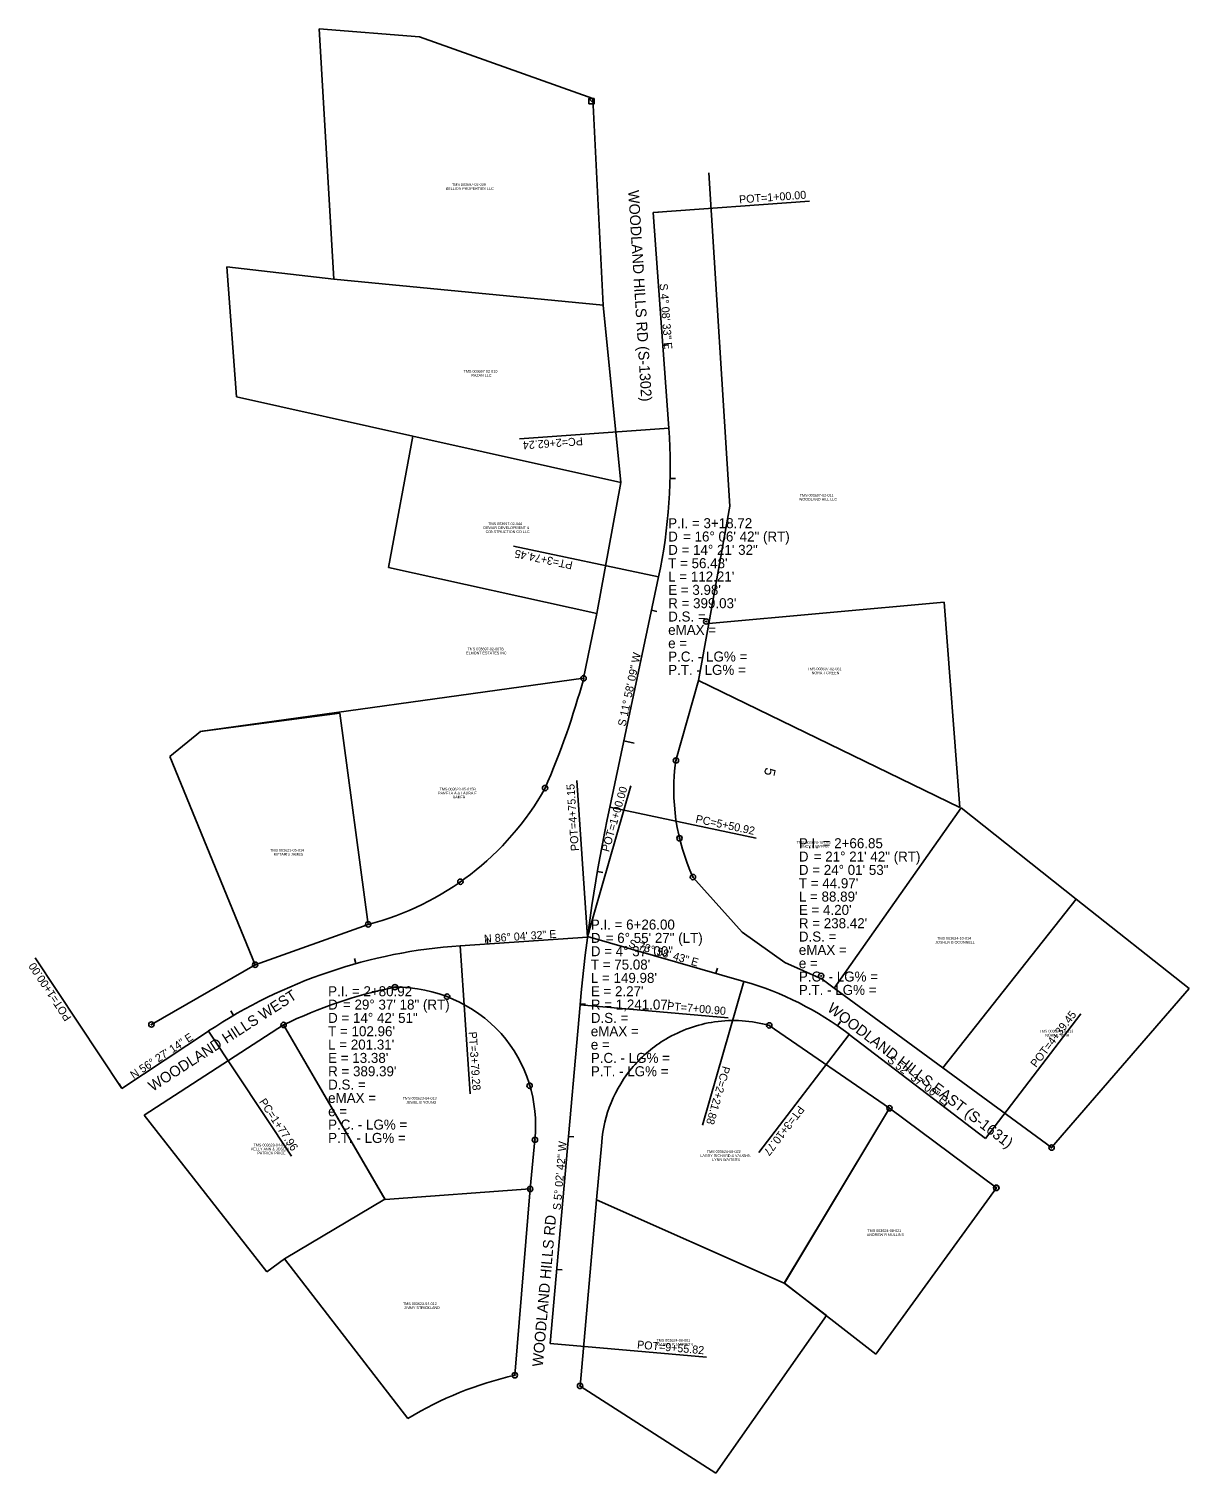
# Model space of a CAD drawing. Extents: x 1963319 to 1964189, y 803266 to 804349.
import ezdxf

# ---------------------------------------------------------------- set-up
doc = ezdxf.new("R2010")
doc.units = 0
for name, color, linetype in [('RD_EX_DV_Prop', 7, 'Continuous'), ('RD_EX_DV_PropPin', 7, 'Continuous'), ('RD_EX_DV_TX_Prop', 7, 'Continuous'), ('RD_HC_CL', 7, 'Continuous'), ('RD_HC_Data', 7, 'Continuous'), ('RD_HC_Data_Tic', 7, 'Continuous'), ('RD_TX_RoadID', 7, 'Continuous')]:
    doc.layers.add(name, color=color, linetype=linetype)

msp = doc.modelspace()

# ---------------------------------------------------------------- linework, layer by layer
at = {"layer": 'RD_EX_DV_Prop'}
for p, q in [((1963547.2, 804161.8), (1963536.2, 804349.4)), ((1963536.2, 804349.4), (1963611.4, 804343.4)), ((1963611.4, 804343.4), (1963741.5, 804297.2)), ((1963741.5, 804297.2), (1963749.2, 804142.2)), ((1963844.2, 803991.6), (1963828.6, 804241.4)), ((1963474.2, 804073.5), (1963467, 804171)), ((1963547.2, 804161.8), (1963467, 804171)), ((1963749.2, 804142.2), (1963547.2, 804161.8)), ((1963762.6, 804009.3), (1963749.2, 804142.2)), ((1963606.4, 804044), (1963474.2, 804073.5)), ((1963588.2, 803945.6), (1963606.4, 804044)), ((1963606.4, 804044), (1963762.6, 804009.3)), ((1963762.6, 804009.3), (1963744.4, 803911)), ((1963828.4, 803903.4), (1963844.2, 803991.6)), ((1963744.4, 803911), (1963588.2, 803945.6)), ((1963828.4, 803903.4), (1964004.9, 803919.4)), ((1964004.9, 803919.4), (1963828.4, 803903.4)), ((1964004.9, 803919.4), (1964016.8, 803765.6)), ((1963734.6, 803862.4), (1963744.4, 803911)), ((1963820.8, 803860.8), (1963828.4, 803903.4)), ((1963446.9, 803822.5), (1963734.6, 803862.4)), ((1963803.8, 803800.8), (1963820.8, 803860.8)), ((1964016.8, 803765.6), (1963820.8, 803860.8)), ((1963424.3, 803803.9), (1963447.3, 803822.6)), ((1964017.6, 803765.2), (1963922.5, 803630.1)), ((1964017.6, 803765.2), (1964103.9, 803696.9)), ((1963816.6, 803713.4), (1963853.5, 803672.1)), ((1964103.9, 803696.9), (1964004, 803570.3)), ((1964103.9, 803696.9), (1964188.7, 803629.9)), ((1963853.5, 803672.1), (1963885.6, 803649.2)), ((1963488.4, 803647.6), (1963410.5, 803602.8)), ((1963885.6, 803649.2), (1963913.4, 803636.9)), ((1963913.4, 803636.9), (1963922.5, 803630.1)), ((1963922.5, 803630.1), (1964004, 803570.3)), ((1964188.7, 803629.9), (1964085.5, 803510.5)), ((1963405, 803534.8), (1963509.6, 803602.5)), ((1963585.7, 803471.5), (1963509.6, 803602.5)), ((1963509.6, 803602.5), (1963585.6, 803471.8)), ((1964004, 803570.3), (1964085.5, 803510.5)), ((1963497.1, 803417.4), (1963405, 803534.8)), ((1963963.9, 803540.1), (1963885, 803408.8)), ((1963698.1, 803516.3), (1963694.5, 803479.5)), ((1963694.5, 803479.5), (1963585.7, 803471.5)), ((1963694.5, 803479.5), (1963683, 803339.8)), ((1964044.1, 803480.4), (1963953.6, 803355.7)), ((1963585.6, 803471.8), (1963510.3, 803427)), ((1963510.3, 803427), (1963497.1, 803417.4)), ((1963602.8, 803307.4), (1963510.3, 803427)), ((1963916.8, 803384.7), (1963833.8, 803266.4))]:
    msp.add_line(p, q, dxfattribs=at)
for points in [[(1963447.3, 803822.6), (1963551.7, 803836.3)], [(1963551.7, 803836.3), (1963573, 803677.9)], [(1963488.4, 803647.6), (1963424.3, 803803.9)], [(1963573, 803677.9), (1963488.4, 803647.6)], [(1963873.8, 803602.1), (1963963.9, 803540.1)], [(1963885.2, 803408.9), (1963964, 803540)], [(1963964, 803540), (1964044.1, 803480.4)], [(1963744.3, 803471.3), (1963748.2, 803514.6)], [(1963732, 803331.6), (1963744.3, 803471.3)], [(1963885, 803408.8), (1963744.3, 803471.3)], [(1963744.3, 803471.3), (1963885, 803408.8)], [(1963885, 803408.8), (1963916.8, 803384.7)], [(1963953.6, 803355.7), (1963885.2, 803408.9)], [(1963833.8, 803266.4), (1963732, 803331.6)]]:
    msp.add_lwpolyline(points, dxfattribs=at)
for centre, radius, start, end in [((1963137.1, 804026.5), 619.7, 336.57, 344.643), ((1963958.5, 803778.9), 156.3, 171.9625, 204.7949), ((1963519.4, 803884.7), 213.7, 284.5471, 330.6702), ((1963659, 803299.8), 337.5, 101.2656, 116.2656), ((1963594, 803524.4), 106.4, 42.2772, 90.5106), ((1963594, 803527.1), 104.6, 354.0595, 41.1595), ((1963742.6, 803076.7), 269.7, 102.7772, 121.221)]:
    msp.add_arc(centre, radius, start, end, dxfattribs=at)
for major_axis, start_param, end_param in [((-64.8, -74.9), 3.997191, 4.391483), ((64.8, 74.9), 0.437838, 0.855627), ((-64.8, -74.9), 4.391466, 4.714868), ((-64.8, -74.9), 4.714866, 5.038268), ((-64.8, -74.9), 5.038267, 5.346337)]:
    msp.add_ellipse((1963846.8, 803506.8), major_axis=major_axis, ratio=0.998737, start_param=start_param, end_param=end_param, dxfattribs=at)
at = {"layer": 'RD_EX_DV_PropPin'}
msp.add_line((1963742.4, 804293.2), (1963738.4, 804297.2), dxfattribs=at)
msp.add_lwpolyline([(1963738.4, 804293.2), (1963738.4, 804297.2), (1963742.4, 804297.2), (1963742.4, 804293.2)], close=True, dxfattribs=at)
for centre, radius in [((1963826.5, 803905), 2), ((1963826.5, 803905), 0.25), ((1963826.5, 803905), 0.0001), ((1963734.6, 803862.4), 2), ((1963734.6, 803862.4), 0.25), ((1963734.6, 803862.4), 0.0001), ((1963803.8, 803800.8), 2), ((1963803.8, 803800.8), 0.25), ((1963803.7, 803800.8), 0.0001), ((1963705.7, 803780.1), 2), ((1963705.7, 803780.1), 0.25), ((1963705.6, 803780.1), 0.0001), ((1963806.5, 803742.5), 2), ((1963806.5, 803742.5), 0.25), ((1963806.5, 803742.6), 0.0001), ((1963642.2, 803709.9), 2), ((1963642.2, 803709.9), 0.25), ((1963642.2, 803709.9), 0.0001), ((1963816.6, 803713.4), 2), ((1963816.6, 803713.4), 0.25), ((1963816.6, 803713.4), 0.0001), ((1963573, 803677.9), 2), ((1963573, 803677.9), 0.25), ((1963573, 803677.9), 0.0001), ((1963488.3, 803647.6), 2), ((1963488.3, 803647.6), 0.25), ((1963488.3, 803647.6), 0.0001), ((1963912.7, 803639.2), 2), ((1963593.1, 803630.8), 2), ((1963593.1, 803630.8), 0.25), ((1963593, 803630.9), 0.0001), ((1963912.7, 803639.2), 0.25), ((1963912.7, 803639.2), 0.0001), ((1963632.2, 803623.7), 2), ((1963632.2, 803623.7), 0.25), ((1963632.1, 803623.7), 0.0001), ((1963410.5, 803602.8), 2), ((1963410.5, 803602.8), 0.25), ((1963410.5, 803602.9), 0.0001), ((1963509.6, 803602.5), 2), ((1963509.6, 803602.5), 0.25), ((1963509.6, 803602.5), 0.0001), ((1963873.8, 803602.1), 2), ((1963873.8, 803602.1), 0.25), ((1963873.8, 803602.1), 0.0001), ((1963694.1, 803556.9), 2), ((1963694.1, 803556.9), 0.25), ((1963694, 803556.9), 0.0001), ((1963964, 803540), 2), ((1963964, 803540), 0.25), ((1963964, 803540.1), 0.0001), ((1963698.1, 803516.3), 2), ((1963698.1, 803516.3), 0.25), ((1963698, 803516.3), 0.0001), ((1964085.5, 803510.5), 2), ((1964085.5, 803510.5), 0.25), ((1964085.4, 803510.5), 0.0001), ((1963694.5, 803479.5), 2), ((1963694.5, 803479.5), 0.25), ((1963694.5, 803479.5), 0.0001), ((1964044, 803480.2), 2), ((1964044.1, 803480.4), 2), ((1964044, 803480.2), 0.25), ((1964044.1, 803480.4), 0.25), ((1964043.9, 803480.2), 0.0001), ((1964044, 803480.4), 0.0001), ((1963683, 803339.8), 2), ((1963683, 803339.8), 0.25), ((1963683, 803339.8), 0.0001), ((1963731.9, 803331.8), 2), ((1963731.9, 803331.8), 0.25), ((1963731.9, 803331.9), 0.0001)]:
    msp.add_circle(centre, radius, dxfattribs=at)
at = {"layer": 'RD_HC_CL'}
for p, q in [((1963786.7, 804211.8), (1963798.4, 804050)), ((1963790.8, 803938.4), (1963754.2, 803765.8)), ((1963641.9, 803661.9), (1963737.6, 803668.4)), ((1963737.6, 803668.8), (1963854.8, 803635.1)), ((1963732, 803617.5), (1963709.6, 803363.6)), ((1963388.4, 803554.8), (1963453.4, 803597.9)), ((1963933.7, 803595.4), (1964036, 803517.3))]:
    msp.add_line(p, q, dxfattribs=at)
for centre, radius, start, end in [((1963400.5, 804021.2), 399, 348.0309, 4.1425), ((1964968.3, 803508.4), 1241.1, 168.0309, 174.9549), ((1963668.6, 803273.4), 389.4, 93.9245, 123.546), ((1963789, 803406), 238.4, 52.6167, 73.9785)]:
    msp.add_arc(centre, radius, start, end, dxfattribs=at)
at = {"layer": 'RD_HC_Data'}
for p, q in [((1963786.7, 804211.8), (1963904.1, 804220.3)), ((1963798.4, 804050), (1963686.5, 804041.9)), ((1963790.8, 803938.4), (1963682, 803961.5)), ((1963737.6, 803668.4), (1963729.5, 803785.8)), ((1963737.6, 803668.8), (1963770.1, 803781.9)), ((1963754.2, 803765.8), (1963863.9, 803742.5)), ((1963388.4, 803554.8), (1963323.4, 803652.9)), ((1963641.9, 803661.9), (1963649.6, 803550.8)), ((1963854.8, 803635.1), (1963823.8, 803527.2)), ((1963732, 803617.5), (1963842.9, 803607.8)), ((1964036, 803517.3), (1964107.4, 803610.7)), ((1963453.4, 803597.9), (1963515.6, 803504.1)), ((1963933.7, 803595.4), (1963866, 803506.8)), ((1963709.6, 803363.6), (1963826.7, 803353.3))]:
    msp.add_line(p, q, dxfattribs=at)
at = {"layer": 'RD_HC_Data_Tic'}
for p, q in [((1963786.7, 804211.8), (1963790.7, 804212.1)), ((1963793.9, 804112.1), (1963797.9, 804112.4)), ((1963799.4, 804012.3), (1963803.4, 804012.2)), ((1963785.5, 803913.4), (1963789.4, 803912.6)), ((1963764.8, 803815.6), (1963772.6, 803813.9)), ((1963745, 803717.6), (1963748.9, 803716.9)), ((1963662.6, 803663.3), (1963662.3, 803667.3)), ((1963737.6, 803668.8), (1963738.7, 803672.6)), ((1963563.9, 803648.5), (1963562.9, 803652.3)), ((1963833.7, 803641.2), (1963834.9, 803645)), ((1963472.1, 803609.6), (1963470.1, 803613)), ((1963732.1, 803618.4), (1963736.1, 803618.1)), ((1963925, 803601.8), (1963927.3, 803605)), ((1963388.4, 803554.8), (1963386.2, 803558.2)), ((1964004.6, 803541.2), (1964007.1, 803544.4)), ((1963723.3, 803518.8), (1963727.3, 803518.5)), ((1963714.5, 803419.2), (1963718.5, 803418.9))]:
    msp.add_line(p, q, dxfattribs=at)

# ---------------------------------------------------------------- texts
at = {"layer": 'RD_EX_DV_TX_Prop'}
for s, p in [('BELLIOS PROPERTIES LLC', (1963631.2, 804228.7)), ('TMS 003697-02-009', (1963635.9, 804231.7)), ('TMS 003697-02-010', (1963644.6, 804091.6)), ('RAZAN LLC', (1963650.3, 804088.6)), ('TMS 003697-02-011', (1963896.7, 803998.7)), ('WOODLAND HILL LLC', (1963896, 803995.7)), ('TMS 003697-02-044', (1963663.1, 803977.3)), ('DEWAR DEVELOPMENT &', (1963659.4, 803974.3)), ('CONSTRUCTION CO LLC', (1963661.1, 803971.3)), ('ELMONT ESTATES INC', (1963646.5, 803880.4)), ('TMS 003697-02-007B', (1963647.5, 803883.4)), ('TMS 003697-02-061', (1963902.6, 803868.5)), ('NORA J GREEN', (1963905.6, 803865.5)), ('PAMELA A & LAURA E', (1963625.5, 803775.3)), ('TMS 003623-05-015B', (1963626.6, 803778.3)), ('BAKER', (1963636.6, 803772.3)), ('TMS 003624-10-015', (1963894.4, 803738.3)), ('TMS 003623-05-014', (1963499.6, 803732.5)), ('MYTARIS JAMES', (1963502.1, 803729.5)), ('JINCY C MYERS', (1963896.9, 803735.3)), ('JOSHUA B OCONNELL', (1963998.2, 803663.5)), ('TMS 003624-10-014', (1963999.8, 803666.5)), ('TMS 003624-10-013', (1964076.5, 803596.8)), ('NORA L MUIR', (1964080.7, 803593.8)), ('TMS 003623-04-013', (1963599, 803546.5)), ('JEWEL B YOUNG', (1963601.5, 803543.5)), ('TMS 003623-04-014', (1963487.1, 803511.4)), ('KELLY ANN & JOSEPH', (1963485.2, 803508.4)), ('PATRICK PRICE', (1963489.9, 803505.4)), ('LARRY RICHARD & VAUGHN', (1963822.2, 803503.5)), ('TMS 003624-08-022', (1963827, 803506.5)), ('LYNN WAITERS', (1963831, 803500.5)), ('ANDREW R MULLINS', (1963947, 803444.2)), ('TMS 003624-08-021', (1963947.4, 803447.2)), ('TMS 003623-04-012', (1963599.1, 803392.4)), ('JIMMY STRICKLAND', (1963599.9, 803389.4)), ('JUANITA P JACKSON', (1963788.6, 803362)), ('TMS 003624-08-001', (1963789.2, 803365))]:
    msp.add_text(s, height=2, dxfattribs=at).set_placement(p)
at = {"layer": 'RD_HC_Data'}
for s, height, rotation, p in [('POT=1+00.00', 6, 4.1425, (1963851.4, 804218.5)), ('S 4%%d 08\' 33" E', 6, 274.1425, (1963791.6, 804158.3)), ('PC=2+62.24', 6, 184.1425, (1963733.8, 804043.3)), ('PT=3+74.45', 6, 168.0309, (1963726.8, 803949.9)), ('S 11%%d 58\' 09" W', 6, 78.0309, (1963766, 803826)), ('5', 8, 258.0309, (1963871, 803796)), ('POT=4+75.15', 6, 93.9245, (1963731.1, 803733.1)), ('POT=1+00.00', 6, 73.9785, (1963753.6, 803731.8)), ('PC=5+50.92', 6, 348.0309, (1963818.2, 803754.3)), ('N 86%%d 04\' 32" E', 6, 3.9245, (1963660.1, 803664.1)), ('S 73%%d 58\' 43" E', 6, 343.9785, (1963767.9, 803661.1)), ('POT=1+00.00', 6, 123.546, (1963350.8, 803607.9)), ('PT=7+00.90', 6, 354.9549, (1963797, 803613.8)), ('POT=4+39.45', 6, 52.6167, (1964073.9, 803570.1)), ('N 56%%d 27\' 14" E', 6, 33.546, (1963397.1, 803561.8)), ('PT=3+79.28', 6, 273.9245, (1963648.4, 803597.2)), ('S 52%%d 37\' 00" E', 6, 322.6167, (1963961.8, 803575.2)), ('PC=2+21.88', 6, 253.9785, (1963838.8, 803572.1)), ('PC=1+77.96', 6, 303.546, (1963491, 803544.9)), ('PT=3+10.77', 6, 232.6167, (1963895.9, 803542.5)), ('S 5%%d 02\' 42" W', 6, 84.9549, (1963717.4, 803463.4)), ('POT=9+55.82', 6, 354.9549, (1963774.5, 803359.9))]:
    msp.add_text(s, height=height, rotation=rotation, dxfattribs=at).set_placement(p)
for s, p in [('P.I. = 3+18.72', (1963798, 803975)), ('D', (1963798, 803965)), ('    = 16%%d 06\' 42" (RT)', (1963798, 803965)), ('D = 14%%d 21\' 32"', (1963798, 803955)), ("T = 56.48'", (1963798, 803945)), ("L = 112.21'", (1963798, 803935)), ("E = 3.98'", (1963798, 803925)), ("R = 399.03'", (1963798, 803915)), ('D.S. = ', (1963798, 803905)), ('eMAX = ', (1963798, 803895)), ('e = ', (1963798, 803885)), ('P.C. - LG% = ', (1963798, 803875)), ('P.T. - LG% = ', (1963798, 803865)), ('P.I. = 2+66.85', (1963896, 803735)), ('D', (1963896, 803725)), ('    = 21%%d 21\' 42" (RT)', (1963896, 803725)), ('D = 24%%d 01\' 53"', (1963896, 803715)), ("T = 44.97'", (1963896, 803705)), ("L = 88.89'", (1963896, 803695)), ("E = 4.20'", (1963896, 803685)), ('P.I. = 6+26.00', (1963740, 803674)), ("R = 238.42'", (1963896, 803675)), ('D', (1963740, 803664)), ('    = 6%%d 55\' 27" (LT)', (1963740, 803664)), ('D.S. = ', (1963896, 803665)), ('D = 4%%d 37\' 00"', (1963740, 803654)), ('eMAX = ', (1963896, 803655)), ("T = 75.08'", (1963740, 803644)), ("L = 149.98'", (1963740, 803634)), ('e = ', (1963896, 803645)), ('P.C. - LG% = ', (1963896, 803635)), ('P.I. = 2+80.92', (1963543, 803624)), ("E = 2.27'", (1963740, 803624)), ('P.T. - LG% = ', (1963896, 803625)), ('D', (1963543, 803614)), ('    = 29%%d 37\' 18" (RT)', (1963543, 803614)), ("R = 1,241.07'", (1963740, 803614)), ('D = 14%%d 42\' 51"', (1963543, 803604)), ('D.S. = ', (1963740, 803604)), ("T = 102.96'", (1963543, 803594)), ('eMAX = ', (1963740, 803594)), ("L = 201.31'", (1963543, 803584)), ('e = ', (1963740, 803584)), ("E = 13.38'", (1963543, 803574)), ('P.C. - LG% = ', (1963740, 803574)), ("R = 389.39'", (1963543, 803564)), ('P.T. - LG% = ', (1963740, 803564)), ('D.S. = ', (1963543, 803554)), ('eMAX = ', (1963543, 803544)), ('e = ', (1963543, 803534)), ('P.C. - LG% = ', (1963543, 803524)), ('P.T. - LG% = ', (1963543, 803514))]:
    msp.add_text(s, height=7.5, dxfattribs=at).set_placement(p)
at = {"layer": 'RD_TX_RoadID'}
for s, rotation, p in [('WOODLAND HILLS RD (S-1302)', 273.5692, (1963768, 804228.2)), ('WOODLAND HILLS WEST', 32.8775, (1963411.4, 803552.3)), ('WOODLAND HILLS EAST (S-1631)', 322.6167, (1963916.7, 803613.5)), ('WOODLAND HILLS RD', 84.9611, (1963704, 803345.9))]:
    msp.add_text(s, height=8, rotation=rotation, dxfattribs=at).set_placement(p)

doc.saveas('drawing.dxf')
